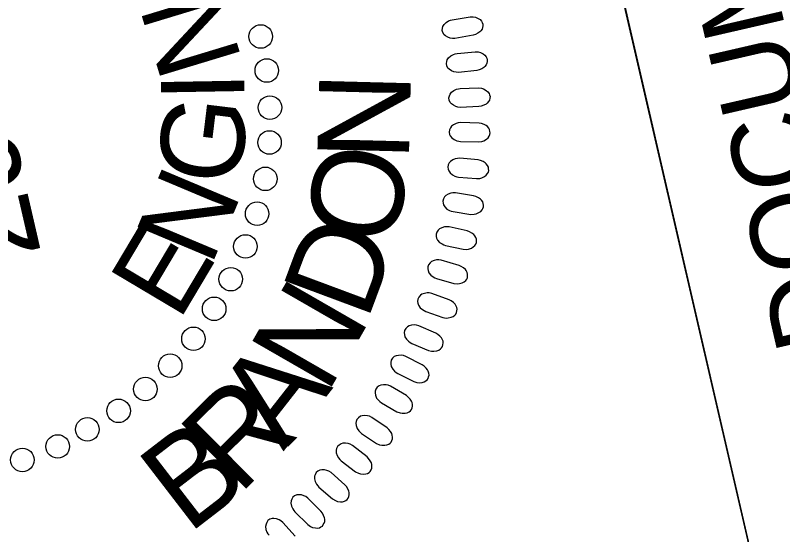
# Model space of a CAD drawing. Extents: x 480532 to 481977, y 491295 to 493182.
# Drawn here: x 480697.1 to 480749.4, y 492772.4 to 492807.8 of the extents above; entities that cross this region are included whole.
import ezdxf

# ---------------------------------------------------------------- set-up
doc = ezdxf.new("R2010")
doc.units = 0
for name, color, linetype in [('Sheet PE Seal Cell', 7, 'Continuous'), ('Sheet Plan CELL', 7, 'Continuous'), ('Sheet Sticker Exception Certification CELL', 7, 'Continuous')]:
    doc.layers.add(name, color=color, linetype=linetype)

msp = doc.modelspace()

# ---------------------------------------------------------------- linework, layer by layer
at = {"layer": 'Sheet PE Seal Cell'}
for points in [[(480726.882, 492807.46), (480728.093, 492807.659), (480728.315, 492807.658), (480728.462, 492807.63), (480728.647, 492807.546), (480728.772, 492807.469), (480728.868, 492807.371), (480728.925, 492807.274), (480728.962, 492807.166), (480728.96, 492807.053), (480728.951, 492806.93), (480728.909, 492806.817), (480728.827, 492806.698), (480728.758, 492806.625), (480728.622, 492806.535), (480728.454, 492806.446), (480728.3, 492806.398), (480727.062, 492806.186), (480726.891, 492806.181), (480726.746, 492806.203), (480726.574, 492806.265), (480726.418, 492806.353), (480726.323, 492806.436), (480726.239, 492806.581), (480726.195, 492806.726), (480726.21, 492806.88), (480726.242, 492806.99), (480726.32, 492807.132), (480726.468, 492807.278), (480726.634, 492807.374), (480726.757, 492807.424)], [(480727.21, 492805.158), (480728.431, 492805.28), (480728.653, 492805.265), (480728.797, 492805.227), (480728.977, 492805.133), (480729.096, 492805.047), (480729.187, 492804.944), (480729.237, 492804.844), (480729.268, 492804.734), (480729.259, 492804.621), (480729.242, 492804.498), (480729.193, 492804.388), (480729.103, 492804.275), (480729.03, 492804.207), (480728.888, 492804.125), (480728.716, 492804.047), (480728.559, 492804.009), (480727.31, 492803.875), (480727.139, 492803.881), (480726.995, 492803.912), (480726.828, 492803.984), (480726.677, 492804.082), (480726.589, 492804.171), (480726.513, 492804.321), (480726.478, 492804.468), (480726.503, 492804.62), (480726.542, 492804.73), (480726.628, 492804.866), (480726.785, 492805.001), (480726.957, 492805.087), (480727.083, 492805.13)], [(480727.424, 492802.779), (480728.65, 492802.825), (480728.87, 492802.796), (480729.012, 492802.749), (480729.186, 492802.643), (480729.299, 492802.55), (480729.383, 492802.441), (480729.427, 492802.338), (480729.451, 492802.227), (480729.435, 492802.115), (480729.41, 492801.993), (480729.354, 492801.887), (480729.258, 492801.778), (480729.181, 492801.715), (480729.034, 492801.643), (480728.856, 492801.576), (480728.698, 492801.548), (480727.443, 492801.493), (480727.272, 492801.509), (480727.131, 492801.549), (480726.968, 492801.632), (480726.825, 492801.739), (480726.741, 492801.833), (480726.676, 492801.987), (480726.65, 492802.137), (480726.685, 492802.287), (480726.73, 492802.394), (480726.824, 492802.524), (480726.99, 492802.65), (480727.167, 492802.724), (480727.295, 492802.758)], [(480727.448, 492799.17), (480728.674, 492799.139), (480728.893, 492799.171), (480729.035, 492799.219), (480729.208, 492799.327), (480729.32, 492799.421), (480729.402, 492799.532), (480729.445, 492799.635), (480729.467, 492799.747), (480729.45, 492799.859), (480729.423, 492799.98), (480729.367, 492800.086), (480729.269, 492800.193), (480729.191, 492800.255), (480729.043, 492800.326), (480728.865, 492800.39), (480728.706, 492800.416), (480727.45, 492800.456), (480727.28, 492800.437), (480727.139, 492800.396), (480726.977, 492800.31), (480726.835, 492800.202), (480726.753, 492800.107), (480726.689, 492799.951), (480726.666, 492799.802), (480726.702, 492799.651), (480726.749, 492799.546), (480726.845, 492799.416), (480727.012, 492799.293), (480727.19, 492799.22), (480727.318, 492799.188)], [(480727.316, 492796.745), (480728.538, 492796.638), (480728.76, 492796.656), (480728.903, 492796.695), (480729.082, 492796.792), (480729.2, 492796.879), (480729.289, 492796.985), (480729.338, 492797.084), (480729.368, 492797.195), (480729.358, 492797.308), (480729.338, 492797.43), (480729.289, 492797.54), (480729.198, 492797.652), (480729.124, 492797.719), (480728.98, 492797.799), (480728.807, 492797.874), (480728.65, 492797.911), (480727.399, 492798.029), (480727.228, 492798.021), (480727.085, 492797.988), (480726.919, 492797.913), (480726.77, 492797.814), (480726.681, 492797.724), (480726.608, 492797.573), (480726.575, 492797.426), (480726.602, 492797.273), (480726.643, 492797.165), (480726.73, 492797.029), (480726.888, 492796.896), (480727.062, 492796.813), (480727.188, 492796.772)], [(480726.933, 492794.391), (480728.146, 492794.206), (480728.368, 492794.21), (480728.514, 492794.24), (480728.699, 492794.326), (480728.822, 492794.405), (480728.917, 492794.505), (480728.973, 492794.602), (480729.009, 492794.71), (480729.006, 492794.823), (480728.995, 492794.947), (480728.952, 492795.059), (480728.868, 492795.177), (480728.799, 492795.249), (480728.661, 492795.337), (480728.492, 492795.424), (480728.338, 492795.47), (480727.097, 492795.666), (480726.926, 492795.669), (480726.781, 492795.645), (480726.61, 492795.581), (480726.455, 492795.492), (480726.361, 492795.407), (480726.278, 492795.261), (480726.236, 492795.115), (480726.254, 492794.962), (480726.288, 492794.851), (480726.366, 492794.711), (480726.516, 492794.567), (480726.684, 492794.473), (480726.807, 492794.425)], [(480726.428, 492792.091), (480727.627, 492791.831), (480727.849, 492791.821), (480727.997, 492791.842), (480728.187, 492791.916), (480728.315, 492791.988), (480728.416, 492792.08), (480728.477, 492792.174), (480728.52, 492792.28), (480728.524, 492792.393), (480728.521, 492792.516), (480728.485, 492792.631), (480728.409, 492792.755), (480728.344, 492792.831), (480728.212, 492792.928), (480728.049, 492793.025), (480727.898, 492793.08), (480726.672, 492793.354), (480726.501, 492793.368), (480726.355, 492793.353), (480726.18, 492793.3), (480726.02, 492793.22), (480725.921, 492793.141), (480725.83, 492793.001), (480725.778, 492792.858), (480725.786, 492792.705), (480725.812, 492792.591), (480725.883, 492792.446), (480726.023, 492792.294), (480726.185, 492792.19), (480726.305, 492792.133)], [(480725.813, 492789.835), (480726.993, 492789.501), (480727.214, 492789.477), (480727.363, 492789.489), (480727.557, 492789.55), (480727.689, 492789.614), (480727.796, 492789.7), (480727.863, 492789.79), (480727.913, 492789.893), (480727.924, 492790.005), (480727.928, 492790.129), (480727.9, 492790.246), (480727.831, 492790.374), (480727.772, 492790.453), (480727.646, 492790.559), (480727.489, 492790.665), (480727.342, 492790.73), (480726.135, 492791.08), (480725.966, 492791.105), (480725.819, 492791.1), (480725.641, 492791.057), (480725.476, 492790.988), (480725.373, 492790.916), (480725.273, 492790.781), (480725.213, 492790.643), (480725.21, 492790.488), (480725.23, 492790.374), (480725.291, 492790.224), (480725.422, 492790.063), (480725.576, 492789.949), (480725.692, 492789.885)], [(480725.081, 492787.596), (480726.239, 492787.188), (480726.458, 492787.15), (480726.607, 492787.153), (480726.805, 492787.202), (480726.94, 492787.257), (480727.052, 492787.336), (480727.125, 492787.421), (480727.181, 492787.521), (480727.2, 492787.633), (480727.212, 492787.756), (480727.189, 492787.874), (480727.13, 492788.006), (480727.075, 492788.09), (480726.957, 492788.203), (480726.807, 492788.319), (480726.664, 492788.393), (480725.482, 492788.818), (480725.314, 492788.853), (480725.168, 492788.857), (480724.987, 492788.826), (480724.818, 492788.767), (480724.711, 492788.701), (480724.601, 492788.574), (480724.534, 492788.439), (480724.522, 492788.285), (480724.534, 492788.169), (480724.585, 492788.017), (480724.705, 492787.848), (480724.852, 492787.724), (480724.964, 492787.653)], [(480724.132, 492785.425), (480725.261, 492784.946), (480725.477, 492784.894), (480725.626, 492784.887), (480725.827, 492784.924), (480725.966, 492784.971), (480726.083, 492785.043), (480726.16, 492785.123), (480726.223, 492785.219), (480726.248, 492785.33), (480726.267, 492785.452), (480726.253, 492785.572), (480726.202, 492785.707), (480726.153, 492785.793), (480726.041, 492785.913), (480725.899, 492786.038), (480725.761, 492786.122), (480724.608, 492786.62), (480724.443, 492786.666), (480724.297, 492786.679), (480724.115, 492786.659), (480723.942, 492786.611), (480723.831, 492786.553), (480723.714, 492786.432), (480723.637, 492786.301), (480723.616, 492786.148), (480723.621, 492786.033), (480723.662, 492785.877), (480723.772, 492785.701), (480723.911, 492785.568), (480724.019, 492785.49)], [(480723.167, 492783.375), (480724.264, 492782.825), (480724.477, 492782.761), (480724.625, 492782.744), (480724.827, 492782.769), (480724.968, 492782.807), (480725.09, 492782.871), (480725.173, 492782.946), (480725.241, 492783.038), (480725.273, 492783.146), (480725.3, 492783.267), (480725.293, 492783.387), (480725.251, 492783.526), (480725.207, 492783.615), (480725.103, 492783.742), (480724.97, 492783.876), (480724.837, 492783.968), (480723.717, 492784.538), (480723.555, 492784.594), (480723.41, 492784.616), (480723.228, 492784.608), (480723.053, 492784.57), (480722.937, 492784.519), (480722.814, 492784.405), (480722.729, 492784.281), (480722.698, 492784.129), (480722.695, 492784.013), (480722.727, 492783.855), (480722.825, 492783.672), (480722.956, 492783.531), (480723.058, 492783.447)], [(480722.055, 492781.385), (480723.116, 492780.767), (480723.324, 492780.689), (480723.471, 492780.664), (480723.674, 492780.675), (480723.818, 492780.704), (480723.943, 492780.761), (480724.03, 492780.831), (480724.104, 492780.918), (480724.143, 492781.024), (480724.177, 492781.143), (480724.179, 492781.264), (480724.144, 492781.404), (480724.106, 492781.496), (480724.011, 492781.63), (480723.886, 492781.771), (480723.759, 492781.872), (480722.677, 492782.511), (480722.52, 492782.577), (480722.376, 492782.608), (480722.193, 492782.611), (480722.017, 492782.585), (480721.899, 492782.541), (480721.767, 492782.436), (480721.675, 492782.316), (480721.634, 492782.167), (480721.625, 492782.051), (480721.646, 492781.891), (480721.733, 492781.703), (480721.854, 492781.554), (480721.951, 492781.463)], [(480720.713, 492779.294), (480721.732, 492778.611), (480721.934, 492778.52), (480722.079, 492778.486), (480722.283, 492778.484), (480722.428, 492778.504), (480722.557, 492778.553), (480722.649, 492778.618), (480722.727, 492778.7), (480722.773, 492778.804), (480722.815, 492778.92), (480722.823, 492779.04), (480722.799, 492779.183), (480722.766, 492779.276), (480722.679, 492779.416), (480722.563, 492779.566), (480722.444, 492779.673), (480721.404, 492780.379), (480721.25, 492780.455), (480721.109, 492780.495), (480720.927, 492780.51), (480720.749, 492780.494), (480720.629, 492780.458), (480720.491, 492780.361), (480720.391, 492780.247), (480720.341, 492780.101), (480720.325, 492779.986), (480720.336, 492779.825), (480720.411, 492779.632), (480720.522, 492779.475), (480720.613, 492779.379)], [(480719.327, 492777.425), (480720.301, 492776.679), (480720.497, 492776.576), (480720.64, 492776.532), (480720.843, 492776.518), (480720.989, 492776.529), (480721.12, 492776.569), (480721.216, 492776.628), (480721.3, 492776.705), (480721.352, 492776.806), (480721.401, 492776.919), (480721.417, 492777.039), (480721.401, 492777.182), (480721.374, 492777.278), (480721.296, 492777.423), (480721.19, 492777.579), (480721.078, 492777.694), (480720.084, 492778.464), (480719.936, 492778.549), (480719.798, 492778.598), (480719.617, 492778.624), (480719.437, 492778.621), (480719.315, 492778.592), (480719.172, 492778.503), (480719.066, 492778.397), (480719.007, 492778.254), (480718.983, 492778.14), (480718.984, 492777.978), (480719.046, 492777.781), (480719.148, 492777.618), (480719.233, 492777.516)], [(480717.808, 492775.635), (480718.734, 492774.829), (480718.924, 492774.714), (480719.063, 492774.66), (480719.265, 492774.635), (480719.412, 492774.636), (480719.545, 492774.668), (480719.644, 492774.721), (480719.733, 492774.792), (480719.791, 492774.89), (480719.847, 492775), (480719.871, 492775.118), (480719.864, 492775.262), (480719.843, 492775.36), (480719.775, 492775.509), (480719.679, 492775.672), (480719.574, 492775.794), (480718.63, 492776.624), (480718.487, 492776.719), (480718.353, 492776.776), (480718.174, 492776.813), (480717.995, 492776.821), (480717.871, 492776.8), (480717.722, 492776.721), (480717.609, 492776.621), (480717.541, 492776.482), (480717.51, 492776.37), (480717.501, 492776.209), (480717.551, 492776.008), (480717.643, 492775.839), (480717.72, 492775.731)], [(480716.17, 492773.948), (480717.044, 492773.085), (480717.226, 492772.958), (480717.362, 492772.897), (480717.562, 492772.857), (480717.708, 492772.849), (480717.844, 492772.873), (480717.945, 492772.92), (480718.038, 492772.986), (480718.103, 492773.08), (480718.165, 492773.186), (480718.197, 492773.302), (480718.199, 492773.447), (480718.184, 492773.545), (480718.125, 492773.698), (480718.039, 492773.867), (480717.942, 492773.995), (480717.053, 492774.883), (480716.917, 492774.986), (480716.785, 492775.052), (480716.609, 492775.101), (480716.431, 492775.119), (480716.306, 492775.106), (480716.153, 492775.036), (480716.034, 492774.944), (480715.957, 492774.81), (480715.919, 492774.7), (480715.901, 492774.539), (480715.937, 492774.335), (480716.018, 492774.161), (480716.089, 492774.049)]]:
    msp.add_lwpolyline(points, close=True, dxfattribs=at)
msp.add_lwpolyline([(480716.18, 492772.291), (480715.348, 492773.233), (480715.218, 492773.345), (480715.091, 492773.419), (480714.918, 492773.478), (480714.742, 492773.507), (480714.616, 492773.503), (480714.46, 492773.442), (480714.334, 492773.357), (480714.25, 492773.228), (480714.205, 492773.121), (480714.176, 492772.963), (480714.2, 492772.756), (480714.27, 492772.577), (480714.333, 492772.461), (480714.409, 492772.355)], dxfattribs=at)
for centre in [(480713.845, 492806.317), (480714.256, 492804.001), (480714.469, 492801.477), (480714.444, 492799.101), (480714.155, 492796.625), (480713.598, 492794.249), (480712.802, 492792.023), (480711.804, 492789.792), (480710.674, 492787.775), (480709.263, 492785.734), (480707.682, 492783.9), (480705.992, 492782.31), (480704.167, 492780.828), (480702.046, 492779.564), (480700.024, 492778.404), (480697.619, 492777.483)]:
    msp.add_circle(centre, 0.801, dxfattribs=at)
at = {"layer": 'Sheet Plan CELL'}
for points in [[(481918.067, 491698.303), (480894.93, 491462.423), (480602.878, 492729.179), (480749.103, 492762.9), (480704.18, 492957.828), (481581.119, 493159.981)], [(480639.493, 492737.62), (480617.018, 492835.113), (480726.655, 492860.387), (480749.103, 492762.9)]]:
    msp.add_lwpolyline(points, close=True, dxfattribs=at)
at = {"layer": 'Sheet Sticker Exception Certification CELL'}
msp.add_line((480749.103, 492762.9), (480704.168, 492957.825), dxfattribs=at)
msp.add_line((480749.103, 492762.9), (480704.168, 492957.825), dxfattribs=at)

# ---------------------------------------------------------------- texts
at = {"layer": 'Sheet PE Seal Cell'}
for s, height, rotation, p in [('29470', 6.2363, 102.9625, (480698.924, 492791.51)), ('N', 5.669, 106.8855, (480712.586, 492804.697)), ('I', 5.669, 91.0059, (480712.744, 492801.908)), ('N', 6.236, 88.5316, (480723.922, 492797.797)), ('G', 5.669, 83.0661, (480712.362, 492796.044)), ('O', 6.236, 78.4318, (480722.858, 492791.854)), ('N', 5.669, 67.1865, (480710.442, 492790.579)), ('E', 5.669, 59.2467, (480708.266, 492786.86)), ('D', 6.236, 69.5635, (480721.076, 492786.86)), ('N', 6.236, 60.0739, (480718.342, 492781.889)), ('A', 6.236, 51.9627, (480715.381, 492778.047)), ('R', 6.236, 44.8458, (480712.359, 492775.049)), ('B', 6.236, 37.5708, (480708.911, 492772.395))]:
    msp.add_text(s, height=height, rotation=rotation, dxfattribs=at).set_placement(p)
at = {"layer": 'Sheet Sticker Exception Certification CELL'}
for s, p in [('UNLESS ALL SIGNATURES COMPLETED', (480764.165, 492782.792)), ('UNLESS ALL SIGNATURES COMPLETED', (480764.165, 492782.792)), ('DOCUMENT NOT CONSIDERED FINAL', (480754.45, 492785.756)), ('DOCUMENT NOT CONSIDERED FINAL', (480754.45, 492785.756))]:
    msp.add_text(s, height=5.5, rotation=102.9811, dxfattribs=at).set_placement(p)

doc.saveas('drawing.dxf')
